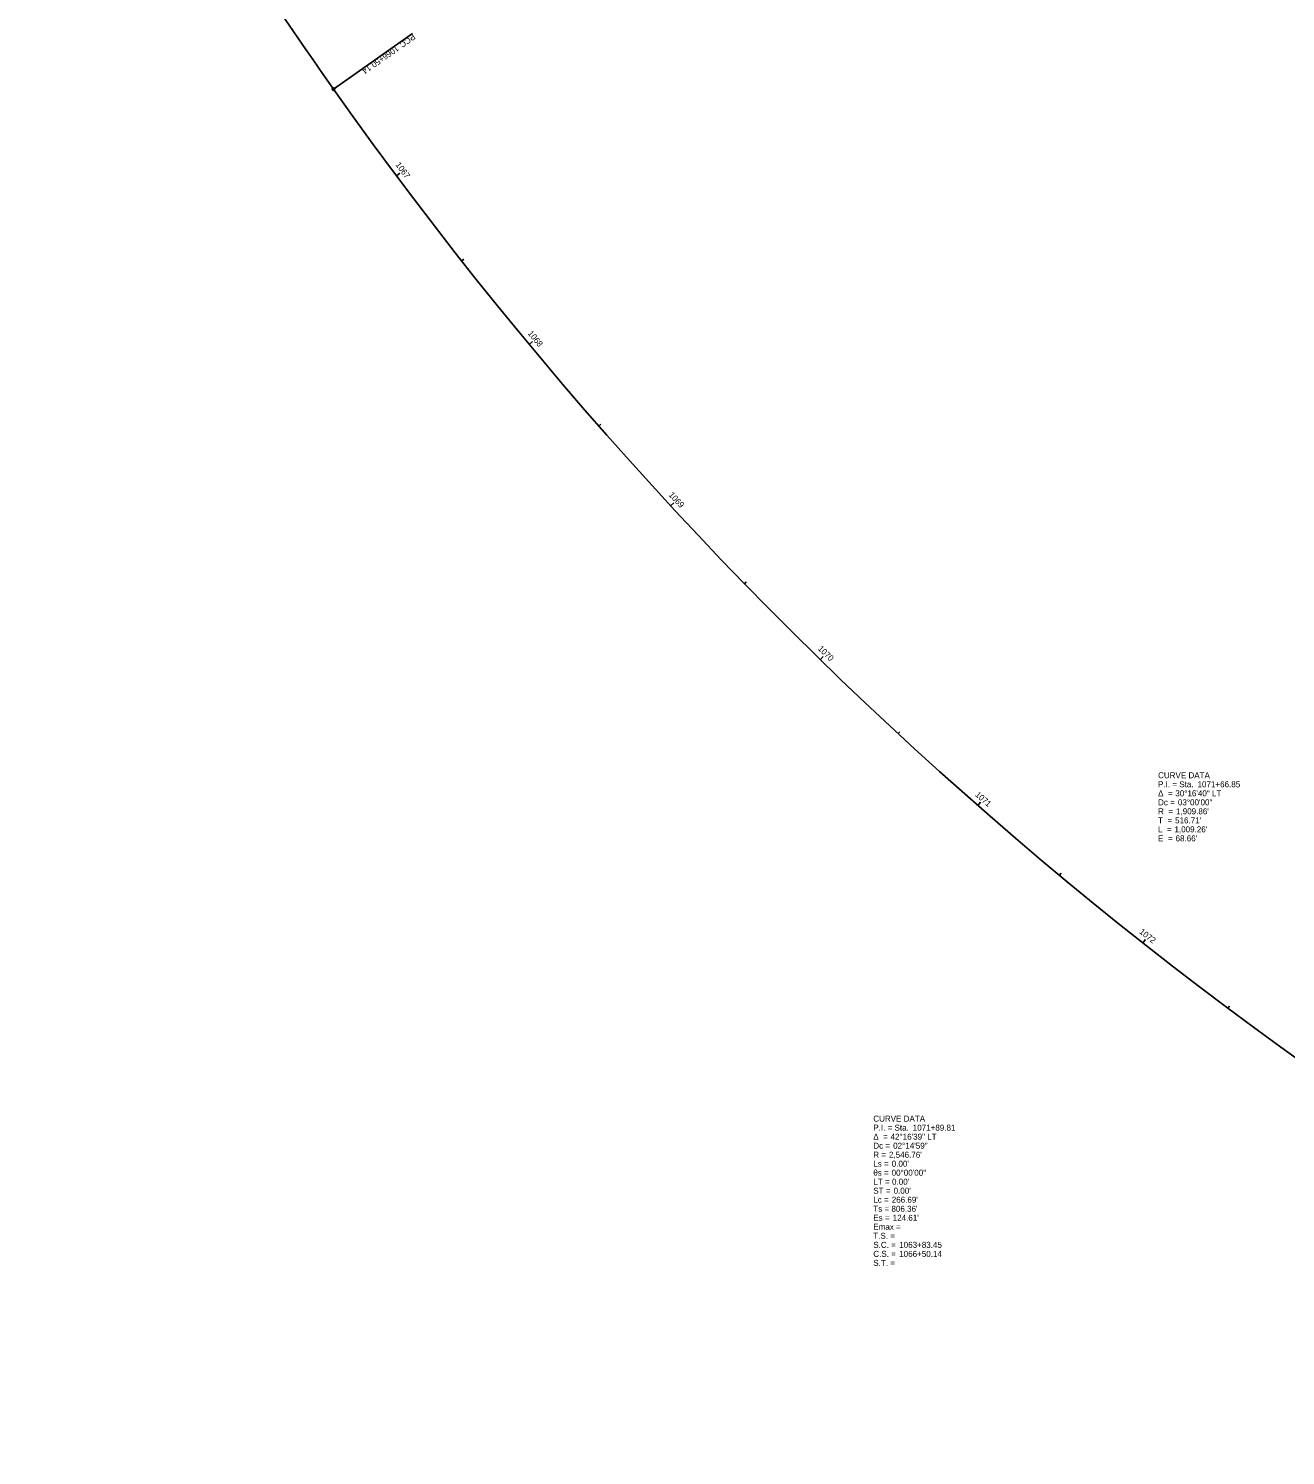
# Model space of a CAD drawing. Extents: x 1948127 to 1949841, y 151410 to 153356.
# Drawn here: x 1948666 to 1949252, y 151508 to 152173 of the extents above; entities that cross this region are included whole.
import ezdxf

# ---------------------------------------------------------------- set-up
doc = ezdxf.new("R2010")
doc.units = 0
for name, color, linetype in [('BR_P_Sub_Deep_Centerline', 7, 'Continuous'), ('BR_P_Sub_Deep_Hidden', 7, 'Continuous'), ('BR_P_Sub_Deep_Object', 7, 'Continuous'), ('SC_Scratch1', 7, 'Continuous')]:
    doc.layers.add(name, color=color, linetype=linetype)

msp = doc.modelspace()

# ---------------------------------------------------------------- linework, layer by layer
at = {"layer": 'BR_P_Sub_Deep_Centerline'}
for p, q in [((1948808.25, 152145.11), (1948809.23, 152145.8)), ((1948837.6, 152104.64), (1948839.21, 152105.83)), ((1948868.01, 152064.94), (1948868.95, 152065.68)), ((1948899.44, 152026.06), (1948900.98, 152027.34)), ((1948931.87, 151988.01), (1948932.78, 151988.8)), ((1948965.3, 151950.82), (1948966.77, 151952.18)), ((1948999.68, 151914.53), (1949000.54, 151915.36)), ((1949035, 151879.14), (1949036.4, 151880.57)), ((1949071.24, 151844.69), (1949072.06, 151845.57)), ((1949108.37, 151811.2), (1949109.69, 151812.7)), ((1949146.36, 151778.7), (1949147.13, 151779.62)), ((1949185.19, 151747.2), (1949186.43, 151748.77)), ((1949224.83, 151716.73), (1949225.54, 151717.69))]:
    msp.add_line(p, q, dxfattribs=at)
at = {"layer": 'BR_P_Sub_Deep_Hidden'}
msp.add_line((1948808.33, 152145), (1948845.1, 152170.94), dxfattribs=at)
msp.add_circle((1948808.33, 152145), 0.6, dxfattribs=at)
at = {"layer": 'SC_Scratch1'}
for centre, radius, start, end in [((1950889.32, 153613.15), 2546.76, 209.20338, 215.20324), ((1950368.9, 153245.99), 1909.86, 215.20324, 245.48103)]:
    msp.add_arc(centre, radius, start, end, dxfattribs=at)

# ---------------------------------------------------------------- texts
at = {"layer": 'BR_P_Sub_Deep_Centerline'}
for s, rotation, p in [('1067', 306.69904, (1948837, 152109.71)), ('1068', 309.69904, (1948898.61, 152031.04)), ('1069', 312.69904, (1948964.23, 151955.74)), ('1070', 315.69904, (1949033.66, 151884.01)), ('1071', 318.69904, (1949106.89, 151815.89)), ('1072', 321.69904, (1949183.34, 151751.9))]:
    msp.add_text(s, height=2.8, rotation=rotation, dxfattribs=at).set_placement(p)
at = {"layer": 'BR_P_Sub_Deep_Hidden'}
for s, p in [('1066+50.14', (1948837.52, 152165.53)), ('PCC', (1948845.16, 152170.92))]:
    msp.add_text(s, height=2.8, rotation=215.20324, dxfattribs=at).set_placement(p)
at = {"layer": 'BR_P_Sub_Deep_Object'}
for s, p in [('CURVE DATA', (1949192.33, 151823.88)), ('P.I. = Sta. ', (1949192.33, 151819.68)), ('1071+66.85', (1949210.7, 151819.68)), ('Δ  = ', (1949192.33, 151815.48)), ('Dc = ', (1949192.33, 151811.28)), ('30°16\'40" LT', (1949200.35, 151815.48)), ('03°00\'00"', (1949201.57, 151811.28)), ('R  = ', (1949192.33, 151807.08)), ("1,909.86'", (1949200.69, 151807.08)), ('T  = ', (1949192.33, 151802.88)), ('L  = ', (1949192.33, 151798.68)), ("1,009.26'", (1949199.97, 151798.68)), ("516.71'", (1949200.26, 151802.88)), ('E  = ', (1949192.33, 151794.48)), ("68.66'", (1949200.48, 151794.48)), ('CURVE DATA', (1949059.7, 151663.89)), ('P.I. = Sta. ', (1949059.7, 151659.69)), ('1071+89.81', (1949078.07, 151659.69)), ('Δ  = ', (1949059.7, 151655.49)), ('Dc = ', (1949059.7, 151651.29)), ('42°16\'39" LT', (1949067.73, 151655.49)), ('02°14\'59"', (1949068.94, 151651.29)), ('R = ', (1949059.7, 151647.09)), ("2,546.76'", (1949066.99, 151647.09)), ('θs = ', (1949059.7, 151638.69)), ('Ls = ', (1949059.7, 151642.89)), ('00°00\'00"', (1949068.24, 151638.69)), ("0.00'", (1949068.29, 151642.89)), ('ST = ', (1949059.7, 151630.29)), ('LT = ', (1949059.7, 151634.49)), ("0.00'", (1949068.43, 151634.49)), ("0.00'", (1949069.16, 151630.29)), ('Lc = ', (1949059.7, 151626.09)), ("266.69'", (1949068.29, 151626.09)), ('Ts = ', (1949059.7, 151621.89)), ('Es = ', (1949059.7, 151617.69)), ("806.36'", (1949068.15, 151621.89)), ("124.61'", (1949068.73, 151617.69)), ('Emax = ', (1949059.7, 151613.49)), ('T.S. = ', (1949059.7, 151609.29)), ('S.C. = ', (1949059.7, 151605.09)), ('1063+83.45', (1949071.77, 151605.09)), ('C.S. = ', (1949059.7, 151600.89)), ('1066+50.14', (1949071.77, 151600.89)), ('S.T. = ', (1949059.7, 151596.69))]:
    msp.add_text(s, height=2.8, dxfattribs=at).set_placement(p)

doc.saveas('drawing.dxf')
